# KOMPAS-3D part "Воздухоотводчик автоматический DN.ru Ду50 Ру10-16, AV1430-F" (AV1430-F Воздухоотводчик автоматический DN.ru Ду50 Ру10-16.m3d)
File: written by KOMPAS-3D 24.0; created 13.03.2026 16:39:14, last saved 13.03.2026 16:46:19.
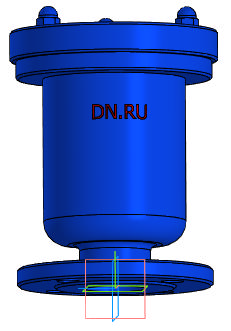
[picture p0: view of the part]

Document properties: Автор: R2D2; Полное имя файла: E:\Работа\Зайцев\AV1430-F Воздухоотводчик автоматический DN.ru Ру10-16 (1)\AV1430-F Воздухоотводчик автоматический DN.ru Ру10-16\DN50\AV1430-F Воздухоотводчик автоматический DN.ru Ду50 Ру10-16.m3d

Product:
- Part/product: Воздухоотводчик автоматический DN.ru Ду50 Ру10-16  | designation AV1430-F
    Масса: 9
    Раздел спецификации: Прочие изделия
    Примечание: D030-00254

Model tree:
1. Операция без истории:1

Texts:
  AV1430-F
